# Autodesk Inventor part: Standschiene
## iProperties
Shininess: 64.0
Length Units: 11269
Angle Units: 11279
Time Units: 11290
Mass Units: 11283
Length Display Precision: 3
Angle Display Precision: 2
Compacted: True
Part Number: Standschiene
Document SubType Name: Modeling
Created: 2005-08
Material: Standard
Designer: Kumpf
Density: 0.0
Volumn: 0.0
Area: 0.0
PropertySet Name: Model Information
Control State: 0
Master: False
Checked Out: False
Author: Kumpf
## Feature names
1. Extrusion1
2. Bohrung1 [Hole]
